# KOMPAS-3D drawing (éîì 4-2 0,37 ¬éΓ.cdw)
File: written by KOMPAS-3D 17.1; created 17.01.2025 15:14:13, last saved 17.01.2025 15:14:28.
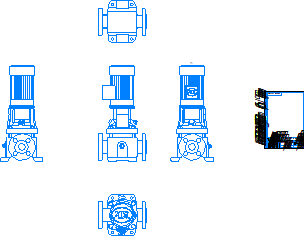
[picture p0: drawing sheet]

Sheet 1: A4, portrait

Title block, sheet 1: name: ВМН 4-2 0,37 кВт; designation: ВМН 4-2 0,37 кВт; sheets: 1; sheet format: A4; stored path: \\adlc.lan\data\АДЛ_ПКД\3D-модели\ADL production\Насосы ГРАНПАМП\Насосы ВМН\ВМН4\KOMPAS 2D\ВМН 4-2 0,37 кВт.cdw

Views: Проекционный вид 2, Проекционный вид 3, Проекционный вид 4, Проекционный вид 5
Referenced files in \\adlc.lan\data\АДЛ_ПКД\3D-модели\ADL production\Насосы ГРАНПАМП\Насосы ВМН\ВМН4\KOMPAS 3D\: ВМН 4-2 0,37 кВт.m3d
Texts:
  Andrey
  АДЛ
Dimensions and other numbers on the sheet: 1:1; 1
